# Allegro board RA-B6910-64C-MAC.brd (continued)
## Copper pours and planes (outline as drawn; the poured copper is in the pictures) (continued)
Net_297 on SIG8: 408.66,43.3 408.66,41.77 410.18,41.77 410.18,43.3
Net_298 on GND9: 408.66,43.3 408.66,41.77 410.18,41.77 410.18,43.3
Net_299 on SIG9: 408.66,43.3 408.66,41.77 410.18,41.77 410.18,43.3
Net_300 on GND10: 408.66,43.3 408.66,41.77 410.18,41.77 410.18,43.3
Net_301 on SIG10: 408.66,43.3 408.66,41.77 410.18,41.77 410.18,43.3
Net_302 on GND11: 408.66,43.3 408.66,41.77 410.18,41.77 410.18,43.3
Net_303 on POWER2: 408.66,43.3 408.66,41.77 410.18,41.77 410.18,43.3
Net_304 on GND12: 408.66,43.3 408.66,41.77 410.18,41.77 410.18,43.3
Net_305 on POWER1: 405.61,43.3 405.61,41.77 407.13,41.77 407.13,43.3
Net_306 on GND2: 405.61,43.3 405.61,41.77 407.13,41.77 407.13,43.3
Net_307 on SIG2: 405.61,43.3 405.61,41.77 407.13,41.77 407.13,43.3
Net_308 on GND3: 405.61,43.3 405.61,41.77 407.13,41.77 407.13,43.3
Net_309 on SIG9: 414.75,43.3 414.75,41.77 416.28,41.77 416.28,43.3
Net_310 on GND10: 414.75,43.3 414.75,41.77 416.28,41.77 416.28,43.3
Net_311 on SIG10: 414.75,43.3 414.75,41.77 416.28,41.77 416.28,43.3
Net_312 on GND11: 414.75,43.3 414.75,41.77 416.28,41.77 416.28,43.3
Net_313 on POWER2: 414.75,43.3 414.75,41.77 416.28,41.77 416.28,43.3
Net_314 on GND12: 414.75,43.3 414.75,41.77 416.28,41.77 416.28,43.3
Net_315 on POWER1: 414.75,40.25 414.75,38.72 416.28,38.72 416.28,40.25
Net_316 on GND2: 414.75,40.25 414.75,38.72 416.28,38.72 416.28,40.25
Net_317 on SIG2: 414.75,40.25 414.75,38.72 416.28,38.72 416.28,40.25
Net_318 on GND3: 414.75,40.25 414.75,38.72 416.28,38.72 416.28,40.25
Net_319 on SIG3: 414.75,40.25 414.75,38.72 416.28,38.72 416.28,40.25
Net_320 on GND4: 414.75,40.25 414.75,38.72 416.28,38.72 416.28,40.25
Net_321 on SIG4: 414.75,40.25 414.75,38.72 416.28,38.72 416.28,40.25
Net_322 on GND5: 414.75,40.25 414.75,38.72 416.28,38.72 416.28,40.25
Net_323 on SIG5: 414.75,40.25 414.75,38.72 416.28,38.72 416.28,40.25
Net_324 on GND6: 414.75,40.25 414.75,38.72 416.28,38.72 416.28,40.25
Net_325 on SIG6: 414.75,40.25 414.75,38.72 416.28,38.72 416.28,40.25
Net_326 on GND7: 414.75,40.25 414.75,38.72 416.28,38.72 416.28,40.25
Net_327 on SIG7: 414.75,40.25 414.75,38.72 416.28,38.72 416.28,40.25
Net_328 on GND8: 414.75,40.25 414.75,38.72 416.28,38.72 416.28,40.25
Net_329 on SIG8: 414.75,40.25 414.75,38.72 416.28,38.72 416.28,40.25
Net_330 on GND9: 414.75,40.25 414.75,38.72 416.28,38.72 416.28,40.25
Net_331 on GND5: 411.71,37.2 411.71,35.68 413.23,35.68 413.23,37.2
Net_332 on GND4: 411.71,37.2 411.71,35.68 413.23,35.68 413.23,37.2
Net_333 on GND3: 411.71,37.2 411.71,35.68 413.23,35.68 413.23,37.2
Net_334 on SIG2: 411.71,37.2 411.71,35.68 413.23,35.68 413.23,37.2
Net_335 on GND2: 411.71,37.2 411.71,35.68 413.23,35.68 413.23,37.2
Net_336 on GND5: 414.75,37.2 414.75,35.68 416.28,35.68 416.28,37.2
Net_337 on GND4: 414.75,37.2 414.75,35.68 416.28,35.68 416.28,37.2
Net_338 on GND3: 414.75,37.2 414.75,35.68 416.28,35.68 416.28,37.2
Net_339 on SIG2: 414.75,37.2 414.75,35.68 416.28,35.68 416.28,37.2
Net_340 on GND2: 414.75,37.2 414.75,35.68 416.28,35.68 416.28,37.2
Net_341 on POWER1: 414.75,37.2 414.75,35.68 416.28,35.68 416.28,37.2
Net_342 on POWER1: 411.71,37.2 411.71,35.68 413.23,35.68 413.23,37.2
Net_343 on SIG8: 414.75,46.34 414.75,44.82 416.28,44.82 416.28,46.34
Net_344 on GND8: 414.75,46.34 414.75,44.82 416.28,44.82 416.28,46.34
Net_345 on SIG7: 414.75,46.34 414.75,44.82 416.28,44.82 416.28,46.34
Net_346 on GND7: 414.75,46.34 414.75,44.82 416.28,44.82 416.28,46.34
Net_347 on SIG6: 414.75,46.34 414.75,44.82 416.28,44.82 416.28,46.34
Net_348 on GND6: 414.75,46.34 414.75,44.82 416.28,44.82 416.28,46.34
Net_349 on SIG5: 414.75,46.34 414.75,44.82 416.28,44.82 416.28,46.34
Net_350 on GND5: 414.75,46.34 414.75,44.82 416.28,44.82 416.28,46.34
Net_351 on SIG4: 414.75,46.34 414.75,44.82 416.28,44.82 416.28,46.34
Net_352 on GND4: 414.75,46.34 414.75,44.82 416.28,44.82 416.28,46.34
Net_353 on SIG3: 414.75,46.34 414.75,44.82 416.28,44.82 416.28,46.34
Net_354 on GND3: 414.75,46.34 414.75,44.82 416.28,44.82 416.28,46.34
Net_355 on SIG2: 414.75,46.34 414.75,44.82 416.28,44.82 416.28,46.34
Net_356 on GND2: 414.75,46.34 414.75,44.82 416.28,44.82 416.28,46.34
Net_357 on POWER1: 414.75,46.34 414.75,44.82 416.28,44.82 416.28,46.34
Net_358 on SIG1: 414.75,46.34 414.75,44.82 416.28,44.82 416.28,46.34
Net_359 on GND12: 411.71,46.34 411.71,44.82 413.23,44.82 413.23,46.34
Net_360 on POWER2: 411.71,46.34 411.71,44.82 413.23,44.82 413.23,46.34
Net_361 on GND11: 411.71,46.34 411.71,44.82 413.23,44.82 413.23,46.34
Net_362 on SIG10: 411.71,46.34 411.71,44.82 413.23,44.82 413.23,46.34
Net_363 on GND10: 411.71,46.34 411.71,44.82 413.23,44.82 413.23,46.34
Net_364 on SIG9: 411.71,46.34 411.71,44.82 413.23,44.82 413.23,46.34
Net_365 on GND9: 411.71,46.34 411.71,44.82 413.23,44.82 413.23,46.34
Net_366 on SIG8: 411.71,46.34 411.71,44.82 413.23,44.82 413.23,46.34
Net_367 on GND8: 411.71,46.34 411.71,44.82 413.23,44.82 413.23,46.34
Net_368 on SIG7: 411.71,46.34 411.71,44.82 413.23,44.82 413.23,46.34
Net_369 on GND7: 411.71,46.34 411.71,44.82 413.23,44.82 413.23,46.34
Net_370 on SIG6: 411.71,46.34 411.71,44.82 413.23,44.82 413.23,46.34
Net_371 on GND6: 411.71,46.34 411.71,44.82 413.23,44.82 413.23,46.34
Net_372 on SIG5: 411.71,46.34 411.71,44.82 413.23,44.82 413.23,46.34
Net_373 on SIG9: 414.75,40.25 414.75,38.72 416.28,38.72 416.28,40.25
Net_374 on GND10: 414.75,40.25 414.75,38.72 416.28,38.72 416.28,40.25
Net_375 on SIG10: 414.75,40.25 414.75,38.72 416.28,38.72 416.28,40.25
Net_376 on GND11: 414.75,40.25 414.75,38.72 416.28,38.72 416.28,40.25
Net_377 on POWER2: 414.75,40.25 414.75,38.72 416.28,38.72 416.28,40.25
Net_378 on GND12: 414.75,40.25 414.75,38.72 416.28,38.72 416.28,40.25
Net_379 on SIG1: 414.75,40.25 414.75,38.72 416.28,38.72 416.28,40.25
Net_380 on SIG1: 414.75,43.3 414.75,41.77 416.28,41.77 416.28,43.3
Net_381 on POWER1: 411.71,43.3 411.71,41.77 413.23,41.77 413.23,43.3
Net_382 on GND2: 411.71,43.3 411.71,41.77 413.23,41.77 413.23,43.3
Net_383 on SIG2: 411.71,43.3 411.71,41.77 413.23,41.77 413.23,43.3
Net_384 on GND3: 411.71,43.3 411.71,41.77 413.23,41.77 413.23,43.3
Net_385 on SIG3: 411.71,43.3 411.71,41.77 413.23,41.77 413.23,43.3
Net_386 on GND4: 411.71,43.3 411.71,41.77 413.23,41.77 413.23,43.3
Net_387 on SIG4: 411.71,43.3 411.71,41.77 413.23,41.77 413.23,43.3
Net_388 on GND5: 411.71,43.3 411.71,41.77 413.23,41.77 413.23,43.3
Net_389 on SIG5: 411.71,43.3 411.71,41.77 413.23,41.77 413.23,43.3
Net_390 on GND6: 411.71,43.3 411.71,41.77 413.23,41.77 413.23,43.3
Net_391 on SIG6: 411.71,43.3 411.71,41.77 413.23,41.77 413.23,43.3
Net_392 on GND7: 411.71,43.3 411.71,41.77 413.23,41.77 413.23,43.3
Net_393 on SIG7: 411.71,43.3 411.71,41.77 413.23,41.77 413.23,43.3
Net_394 on GND8: 411.71,43.3 411.71,41.77 413.23,41.77 413.23,43.3
Net_395 on SIG8: 411.71,43.3 411.71,41.77 413.23,41.77 413.23,43.3
Net_396 on GND9: 411.71,43.3 411.71,41.77 413.23,41.77 413.23,43.3
Net_397 on SIG9: 411.71,43.3 411.71,41.77 413.23,41.77 413.23,43.3
Net_398 on GND10: 411.71,43.3 411.71,41.77 413.23,41.77 413.23,43.3
Net_399 on SIG10: 411.71,43.3 411.71,41.77 413.23,41.77 413.23,43.3
Net_400 on GND11: 411.71,43.3 411.71,41.77 413.23,41.77 413.23,43.3
Net_401 on POWER2: 411.71,43.3 411.71,41.77 413.23,41.77 413.23,43.3
Net_402 on GND12: 411.71,43.3 411.71,41.77 413.23,41.77 413.23,43.3
Net_403 on POWER1: 411.71,40.25 411.71,38.72 413.23,38.72 413.23,40.25
Net_404 on GND2: 411.71,40.25 411.71,38.72 413.23,38.72 413.23,40.25
Net_405 on SIG2: 411.71,40.25 411.71,38.72 413.23,38.72 413.23,40.25
Net_406 on GND3: 411.71,40.25 411.71,38.72 413.23,38.72 413.23,40.25
Net_407 on SIG3: 411.71,40.25 411.71,38.72 413.23,38.72 413.23,40.25
Net_408 on GND4: 411.71,40.25 411.71,38.72 413.23,38.72 413.23,40.25
Net_409 on SIG4: 411.71,40.25 411.71,38.72 413.23,38.72 413.23,40.25
Net_410 on GND5: 411.71,40.25 411.71,38.72 413.23,38.72 413.23,40.25
Net_411 on SIG5: 411.71,40.25 411.71,38.72 413.23,38.72 413.23,40.25
Net_412 on GND6: 411.71,40.25 411.71,38.72 413.23,38.72 413.23,40.25
Net_413 on SIG6: 411.71,40.25 411.71,38.72 413.23,38.72 413.23,40.25
Net_414 on GND7: 411.71,40.25 411.71,38.72 413.23,38.72 413.23,40.25
Net_415 on SIG7: 411.71,40.25 411.71,38.72 413.23,38.72 413.23,40.25
Net_416 on GND8: 411.71,40.25 411.71,38.72 413.23,38.72 413.23,40.25
Net_417 on SIG8: 411.71,40.25 411.71,38.72 413.23,38.72 413.23,40.25
Net_418 on GND9: 411.71,40.25 411.71,38.72 413.23,38.72 413.23,40.25
Net_419 on SIG9: 411.71,40.25 411.71,38.72 413.23,38.72 413.23,40.25
Net_420 on GND10: 411.71,40.25 411.71,38.72 413.23,38.72 413.23,40.25
Net_421 on SIG10: 411.71,40.25 411.71,38.72 413.23,38.72 413.23,40.25
Net_422 on GND11: 411.71,40.25 411.71,38.72 413.23,38.72 413.23,40.25
Net_423 on POWER2: 411.71,40.25 411.71,38.72 413.23,38.72 413.23,40.25
Net_424 on GND12: 411.71,40.25 411.71,38.72 413.23,38.72 413.23,40.25
Net_425 on SIG1: 411.71,40.25 411.71,38.72 413.23,38.72 413.23,40.25
Net_426 on SIG1: 411.71,43.3 411.71,41.77 413.23,41.77 413.23,43.3
Net_427 on POWER1: 414.75,43.3 414.75,41.77 416.28,41.77 416.28,43.3
Net_428 on GND2: 414.75,43.3 414.75,41.77 416.28,41.77 416.28,43.3
Net_429 on SIG2: 414.75,43.3 414.75,41.77 416.28,41.77 416.28,43.3
Net_430 on GND3: 414.75,43.3 414.75,41.77 416.28,41.77 416.28,43.3
Net_431 on SIG3: 414.75,43.3 414.75,41.77 416.28,41.77 416.28,43.3
Net_432 on GND4: 414.75,43.3 414.75,41.77 416.28,41.77 416.28,43.3
Net_433 on SIG4: 414.75,43.3 414.75,41.77 416.28,41.77 416.28,43.3
Net_434 on GND5: 414.75,43.3 414.75,41.77 416.28,41.77 416.28,43.3
Net_435 on SIG5: 414.75,43.3 414.75,41.77 416.28,41.77 416.28,43.3
Net_436 on GND6: 414.75,43.3 414.75,41.77 416.28,41.77 416.28,43.3
Net_437 on SIG6: 414.75,43.3 414.75,41.77 416.28,41.77 416.28,43.3
Net_438 on GND7: 414.75,43.3 414.75,41.77 416.28,41.77 416.28,43.3
Net_439 on SIG7: 414.75,43.3 414.75,41.77 416.28,41.77 416.28,43.3
Net_440 on GND8: 414.75,43.3 414.75,41.77 416.28,41.77 416.28,43.3
Net_441 on SIG8: 414.75,43.3 414.75,41.77 416.28,41.77 416.28,43.3
Net_442 on GND9: 414.75,43.3 414.75,41.77 416.28,41.77 416.28,43.3
Net_443 on GND5: 411.71,46.34 411.71,44.82 413.23,44.82 413.23,46.34
Net_444 on SIG4: 411.71,46.34 411.71,44.82 413.23,44.82 413.23,46.34
Net_445 on GND4: 411.71,46.34 411.71,44.82 413.23,44.82 413.23,46.34
Net_446 on SIG3: 411.71,46.34 411.71,44.82 413.23,44.82 413.23,46.34
Net_447 on GND3: 411.71,46.34 411.71,44.82 413.23,44.82 413.23,46.34
Net_448 on SIG2: 411.71,46.34 411.71,44.82 413.23,44.82 413.23,46.34
Net_449 on GND2: 411.71,46.34 411.71,44.82 413.23,44.82 413.23,46.34
Net_450 on POWER1: 411.71,46.34 411.71,44.82 413.23,44.82 413.23,46.34
Net_451 on SIG1: 411.71,46.34 411.71,44.82 413.23,44.82 413.23,46.34
Net_452 on GND12: 414.75,46.34 414.75,44.82 416.28,44.82 416.28,46.34
Net_453 on POWER2: 414.75,46.34 414.75,44.82 416.28,44.82 416.28,46.34
Net_454 on GND11: 414.75,46.34 414.75,44.82 416.28,44.82 416.28,46.34
Net_455 on SIG10: 414.75,46.34 414.75,44.82 416.28,44.82 416.28,46.34
Net_456 on GND10: 414.75,46.34 414.75,44.82 416.28,44.82 416.28,46.34
Net_457 on SIG9: 414.75,46.34 414.75,44.82 416.28,44.82 416.28,46.34
Net_458 on GND9: 414.75,46.34 414.75,44.82 416.28,44.82 416.28,46.34
Net_459 on TOP (solid shape): outline of 184 points within 387.8,37.08 391.35,40.64
Net_460 on BOTTOM (solid shape): outline of 184 points within 387.8,37.08 391.35,40.64
Net_461 on BOTTOM (solid shape): outline of 184 points within 411.95,212.07 415.51,215.62
Net_462 on TOP (solid shape): outline of 184 points within 411.95,212.07 415.51,215.62
PCIE_PVDD0P8 on TOP: 165.93,184.78 165.93,183.13 165.54,182.75 161.35,182.75 161.23,182.88 161.23,184.78 161.35,184.91 165.8,184.91
PCIE_PVDD0P8 on SIG3: 185.36,181.99 189.67,177.67 189.67,168.27 188.91,167.51 188.91,157.22 189.42,156.72 193.74,156.72 194.12,157.1 194.12,157.86 193.23,158.75 193.23,167.13 192.21,168.15 192.21,178.18 185.48,184.91 164.66,184.91 164.65,184.91 161.92,184.91 161.64,184.63 161.64,182.71 162.36,181.99
PCIE_TRVDD0P8 on TOP: 209.99,192.78 211.66,192.78 211.66,194.07 211.9,194.31 211.9,196.34 211.77,196.47 209.99,196.47 209.87,196.34 209.87,192.91
PCIE_TRVDD0P8 on SIG8: 200.09,164.72 202.76,164.72 203.14,165.1 203.14,179.58 212.41,188.85 212.41,194.05 212.03,194.43 208.6,194.43 208.22,194.05 208.22,190.75 199.96,182.5 199.96,164.84
PH1 on TOP (solid shape): 79.27,135.09 84.68,135.09 85.03,134.74 85.03,131.44 84.75,131.16 73.04,131.16 72.78,131.42 72.78,134.97 72.91,135.1 79.26,135.1
PH2 on TOP (solid shape): 79.27,145.25 84.68,145.25 85.03,144.9 85.03,141.73 84.62,141.32 73.04,141.32 72.78,141.58 72.78,145.13 72.91,145.26 79.26,145.26
PH3 on TOP (solid shape): 84.83,155.03 84.83,151.94 84.38,151.48 73.04,151.48 72.78,151.74 72.78,155.29 72.91,155.42 84.44,155.42
PH4 on TOP (solid shape): 84.83,165.18 84.83,162.28 84.2,161.64 73.04,161.64 72.78,161.9 72.78,165.45 72.91,165.58 84.43,165.58
PH5 on TOP (solid shape): 84.88,175.41 84.88,172.2 84.49,171.8 73.04,171.8 72.78,172.06 72.78,175.61 72.91,175.74 84.55,175.74
PH6 on TOP (solid shape): 84.85,185.67 84.85,182.39 84.42,181.96 73.04,181.96 72.78,182.22 72.78,185.77 72.91,185.9 84.62,185.9
PH7 on TOP (solid shape): 343.31,144.57 343.31,141.02 343.18,140.89 331.15,140.89 330.9,141.14 330.9,144.7 331.03,144.83 343.06,144.83
PH8 on TOP (solid shape): 343.31,134.41 343.31,130.86 343.18,130.73 331.1,130.73 330.9,130.93 330.9,134.41 331.15,134.67 343.06,134.67
PH9 on TOP (solid shape): 343.31,164.89 343.31,161.34 343.18,161.21 331.1,161.21 330.9,161.41 330.9,165.02 331.03,165.15 343.06,165.15
PH10 on TOP (solid shape): 343.31,154.73 343.31,151.18 343.18,151.05 331.15,151.05 330.9,151.3 330.9,154.86 331.03,154.99 343.06,154.99
PH11 on TOP: 331.03,185.67 343.09,185.67 343.34,185.42 343.34,181.61 343.09,181.35 331.03,181.35 330.77,181.61 330.77,185.42
PH12 on TOP (solid shape): 343.31,175.05 343.31,171.5 343.18,171.37 331.1,171.37 330.9,171.57 330.9,175.05 331.15,175.31 343.06,175.31
PVTMON_AVDD1P8 on TOP: 186.37,178.69 187.52,177.54 187.52,175.53 186.61,174.62 186.4,174.62 185.32,175.7 183.89,175.7 182.18,177.42 182.18,178.43 182.44,178.69
PVTMON_AVDD1P8 on SIG8: 216.47,153.92 216.85,153.54 216.85,125.98 216.47,125.6 193.01,125.6 192.16,126.45 184.54,126.45 183.7,125.6 178.75,125.6 178.24,126.11 178.24,138.38 179.77,139.9 179.77,149.98 177.74,152.02 177.74,153.79 177.99,154.05 179.26,154.05 183.83,158.62 183.83,175.26 184.47,175.89 185.99,175.89 186.75,175.13 186.75,173.48 186.25,172.97 186.25,160.27 186.5,160.02 187.9,160.02 189.17,158.75 189.17,156.97 189.18,156.96 189.18,155.51 190.76,153.92
RESCAL_AVDD0P8 on TOP: 180.53,178.69 180.66,178.56 180.66,177.24 181.01,177.24 182.86,175.38 185.31,175.38 186.31,174.38 186.68,174.38 187.86,175.57 193.12,175.57 193.39,175.3 193.39,173.96 193.19,173.76 188.46,173.76 187.88,173.17 186.19,173.17 185.65,173.72 179.15,173.72 176.09,176.78 176.09,178.56 176.21,178.69
RESCAL_AVDD0P8 on SIG10: 177.99,154.94 179.9,154.94 180.78,154.05 191.45,154.05 191.83,154.43 191.83,173.14 190.72,174.25 190.72,175.1 191.24,175.63 195.53,175.63 197.29,173.86 197.29,152.4 198.44,151.25 214.44,151.25 215.84,152.65 215.84,154.94 215.96,155.06 217.67,155.06 217.92,154.82 217.92,148.89 215.2,146.17 215.2,133.09 217.23,131.06 217.23,126.87 217.11,126.74 178.5,126.74 177.86,127.38 177.86,154.81
TS_PLL_AVDD1P8 on TOP: 223.33,192.78 225.11,192.78 225.23,192.91 225.23,194.69 225.11,194.82 223.33,194.82 223.2,194.69 223.2,192.91
TS_PLL_AVDD1P8 on SIG8: 196.91,154.05 200.6,154.05 200.85,154.3 200.85,162.3 199.58,163.57 199.58,182.75 207.58,190.75 207.58,194.43 208.09,194.94 220.66,194.94 222.95,192.66 224.73,192.66 224.85,192.78 224.85,197.48 223.84,198.5 204.79,198.5 201.49,195.2 201.49,189.74 196.66,184.91 196.66,154.3
USB5V on TOP: 391.86,214.17 391.86,216.07 391.73,216.2 388.81,216.2 388.68,216.33 388.68,223.56 388.3,223.95 386.52,223.95 386.14,223.56 386.14,216.58 385.61,216.05 385.61,215.54 385.89,215.26 386.68,215.26 387.92,214.02 391.71,214.02
USB5V on TOP: 394.91,26.79 396.68,26.79 396.81,26.92 396.81,29.84 396.68,29.97 394.91,29.97 394.78,29.84 394.78,26.92
USB5V on BOTTOM: 383.48,212.72 391.48,212.72 391.86,213.1 391.86,221.87 390.59,223.14 386.27,223.14 385.51,222.37 385.51,219.96 383.22,217.68 383.22,212.98
USB5V on SIG2: 394.85,27.56 396.47,27.56 396.91,27.99 396.91,48.17 397.61,48.87 398.56,48.87 411.67,61.97 411.67,214.25 408.62,217.29 399.48,217.29 393.76,223.01 385.64,223.01 384.62,221.99 384.62,217.55 385.38,216.79 385.38,204.21 393.38,196.21 393.38,67.05 388.68,62.35 388.68,33.72
VMON_PWM_OUT on SIG4: 27.24,173.1 28.89,171.45 28.89,167.76 31.05,165.61 31.05,157.1 30.42,156.46 26.61,156.46 25.59,157.48 25.59,165.99 21.15,170.43 14.67,170.43 14.29,170.81 14.29,172.84 14.54,173.1
ZQSFP+1_3.3V on TOP (solid shape): 20.97,110.11 21,110.09 21.02,110.06 21.02,109.42 21.88,109.42 21.88,110.06 21.9,110.09 21.93,110.11 22.21,110.11 22.25,110.09 22.26,110.06 22.26,109.42 23.13,109.42 23.13,110.06 23.14,110.09 23.18,110.11 23.33,110.11 23.37,110.09 23.38,110.06 23.38,109.42 24.25,109.42 24.25,110.06 24.26,110.09 24.3,110.11 24.83,110.11 25.34,109.6 29.02,109.6 29.27,109.34 29.27,105.53 28.33,104.59 28.22,104.57 28.16,104.65 27.51,104.89 27.74,104.24 27.83,104.17 27.81,104.07 27.62,103.88 27.11,103.88 26.73,103.5 26.73,102.49 26.23,101.98 25.87,101.98 25.85,102 25.84,102.02 25.46,102.36 25.08,102.02 25.07,101.99 25.03,101.98 7.81,101.98 7.3,102.49 7.3,109.47 7.94,110.11
ZQSFP+1_3.3V on BOTTOM (solid shape): 26.73,109.85 26.73,106.04 26.23,105.53 23.43,105.53 23.18,105.28 23.18,102.23 22.92,101.98 7.81,101.98 7.3,102.49 7.3,103.38 7.05,103.63 4.89,103.63 4.64,103.88 4.64,105.79 4.89,106.04 6.92,106.04 7.3,106.42 7.3,109.47 7.94,110.11 26.48,110.11
ZQSFP+1_3.3V on TOP: 49.21,90.8 49.59,90.42 49.59,85.98 49.47,85.85 48.32,85.85 48.13,86.04 48.13,86.93 47.56,87.5 46.8,87.5 46.55,87.75 46.55,90.55 46.8,90.8
ZQSFP+1_3.3V on TOP: 13.14,83.56 9.46,83.56 9.33,83.69 9.33,87.9 9.44,88.01 13.16,88.01 13.27,87.9 13.27,87.37 13.27,87.37 13.27,83.69
ZQSFP+1_3.3V on TOP: 13.02,77.47 9.33,77.47 9.21,77.59 9.21,79.25 9.59,79.63 12.76,79.63 13.14,79.25 13.14,77.59
ZQSFP+1_3.3V on TOP: 28.87,93.41 28.45,93.41 28.32,93.53 28.32,95.18 28.7,95.56 31.88,95.56 32.26,95.18 32.26,93.53 31.83,93.1 29.18,93.1
ZQSFP+1_3.3V on TOP: 32.26,99.57 28.58,99.57 28.45,99.69 28.45,103.38 29.72,104.65 31.81,104.65 32.39,104.07 32.39,99.69
ZQSFP+1_3.3V on TOP: 67.25,86.87 63.56,86.87 63.44,86.99 63.44,90.68 63.69,90.93 67.12,90.93 67.37,90.68 67.37,86.99
ZQSFP+1_3.3V on TOP: 89.85,87.12 89.85,90.68 90.11,90.93 93.54,90.93 93.79,90.68 93.79,87.12 93.66,86.99 89.98,86.99
ZQSFP+1_3.3V on TOP: 49.47,81.02 45.78,81.02 45.66,81.15 45.66,82.42 45.78,82.55 46.55,82.55 47.18,83.18 49.21,83.18 49.59,82.8 49.59,81.15
ZQSFP+1_3.3V on TOP, BOTTOM: 67.25,81.02 63.56,81.02 63.44,81.15 63.44,82.8 63.82,83.18 66.99,83.18 67.37,82.8 67.37,81.15
ZQSFP+1_3.3V on TOP, BOTTOM: 89.85,81.4 89.85,82.8 90.23,83.18 90.74,83.18 91.25,83.69 92.39,83.69 92.9,83.18 93.41,83.18 93.79,82.8 93.79,81.4 93.66,81.28 89.98,81.28
ZQSFP+1_3.3V on TOP, BOTTOM: 80.45,86.87 76.77,86.87 76.64,86.99 76.64,90.68 76.9,90.93 80.33,90.93 80.58,90.68 80.58,86.99
ZQSFP+1_3.3V on TOP, BOTTOM: 80.45,81.02 76.77,81.02 76.64,81.15 76.64,82.8 77.03,83.18 80.2,83.18 80.58,82.8 80.58,81.15
ZQSFP+1_3.3V on BOTTOM: 89.85,87.12 89.85,92.71 90.23,93.09 100.52,93.09 100.9,92.71 100.9,87.25 100.65,86.99 99.12,86.99 99,87.12 99,90.68 98.23,91.44 93.92,91.44 93.79,91.31 93.79,87.12 93.66,86.99 89.98,86.99
ZQSFP+1_3.3V on BOTTOM: 13.08,77.66 9.4,77.66 9.27,77.78 9.27,79.44 9.65,79.82 12.83,79.82 13.21,79.44 13.21,77.78
ZQSFP+1_3.3V on BOTTOM: 30.61,93.09 30.29,93.41 28.45,93.41 28.32,93.53 28.32,95.18 28.7,95.56 30.73,95.56 31.26,96.09 33.27,96.09 33.46,95.9 33.46,95.67 33.06,95.28 32.83,95.28 32.58,95.03 32.58,93.34 32.32,93.09
ZQSFP+1_3.3V on BOTTOM: 13.08,83.69 9.4,83.69 9.27,83.82 9.27,87.37 9.53,87.63 13.08,87.63 13.21,87.5 13.21,83.82
ZQSFP+1_3.3V on BOTTOM: 49.47,81.02 45.78,81.02 45.66,81.15 45.66,82.8 46.04,83.18 49.21,83.18 49.59,82.8 49.59,81.15
ZQSFP+1_3.3V on BOTTOM: 67.25,86.87 63.56,86.87 63.44,86.99 63.44,93.47 63.69,93.72 66.99,93.72 67.37,93.34 67.37,86.99
ZQSFP+1_3.3V on BOTTOM: 32.26,99.57 28.58,99.57 28.45,99.69 28.45,104.14 28.96,104.65 31.88,104.65 32.39,104.14 32.39,99.69
ZQSFP+1_3.3V on BOTTOM: 49.53,87.12 45.85,87.12 45.72,87.25 45.72,92.58 45.97,92.83 49.28,92.83 49.66,92.45 49.66,87.25
ZQSFP+1_3.3V on BOTTOM: 40.96,98.42 40.96,93.85 40.58,93.47 38.54,93.47 38.29,93.72 38.29,95.12 37.66,95.76 37.66,98.42 37.91,98.68 40.7,98.68
ZQSFP+1_3.3V on POWER1: 1.02,112.25 1.93,113.15 41.08,113.15 41.08,106 37.53,102.44 37.53,99.36 39.31,97.58 39.31,94.91 42.78,91.44 51.03,91.44 52.69,89.79 63.14,89.79 64.54,91.18 74.28,91.18 74.91,90.55 78.25,90.55 78.63,90.93 81.39,90.93 83.93,88.39 87.27,88.39 90.06,91.18 91.8,91.18 92.27,90.72 92.27,69.39 92.24,69.36 92.24,52.42 91.76,51.94 15.56,51.94 12.64,54.86 2.35,54.86 1.02,56.2
ZQSFP+2_3.3V on TOP (solid shape): 48.65,117.09 48.69,117.08 48.7,117.04 48.7,116.41 49.57,116.41 49.57,117.04 49.58,117.08 49.62,117.09 49.9,117.09 49.93,117.08 49.95,117.04 49.95,116.41 50.81,116.41 50.81,117.04 50.83,117.08 50.86,117.09 51.02,117.09 51.05,117.08 51.07,117.04 51.07,116.41 51.93,116.41 51.93,117.04 51.95,117.08 51.98,117.09 54.17,117.09 54.42,116.84 54.42,109.34 53.91,108.84 35.5,108.84 34.99,109.34 34.99,116.46 35.62,117.09
ZQSFP+2_3.3V on BOTTOM (solid shape): 54.42,116.84 54.42,110.87 52.64,109.09 36.26,109.09 34.73,110.61 32.58,110.61 32.32,110.87 32.32,112.77 32.58,113.03 34.61,113.03 34.99,113.41 34.99,116.46 35.62,117.09 54.17,117.09
ZQSFP+2_3.3V on TOP: 170.62,90.68 171.01,91.06 174.18,91.06 174.56,90.68 174.56,86.48 174.43,86.36 170.75,86.36 170.62,86.48
ZQSFP+2_3.3V on TOP: 130.24,86.87 126.56,86.87 126.43,86.99 126.43,90.68 126.68,90.93 130.11,90.93 130.37,90.68 130.37,86.99
ZQSFP+2_3.3V on TOP: 130.24,81.02 126.56,81.02 126.43,81.15 126.43,82.42 127.19,83.18 129.98,83.18 130.37,82.8 130.37,81.15
ZQSFP+2_3.3V on TOP: 187.64,81.02 183.96,81.02 183.83,81.15 183.83,82.8 184.21,83.18 187.39,83.18 187.77,82.8 187.77,81.15
ZQSFP+2_3.3V on TOP: 187.64,86.87 183.96,86.87 183.83,86.99 183.83,90.68 184.21,91.06 187.39,91.06 187.77,90.68 187.77,86.99
ZQSFP+2_3.3V on TOP: 174.43,81.02 170.75,81.02 170.62,81.15 170.62,82.8 170.92,83.1 174.27,83.1 174.56,82.8 174.56,81.15
ZQSFP+2_3.3V on TOP: 143.45,86.87 139.76,86.87 139.64,86.99 139.64,90.93 139.76,91.06 143.32,91.06 143.57,90.8 143.57,86.99
ZQSFP+2_3.3V on TOP: 161.23,86.87 157.67,86.87 157.54,86.99 157.54,88.77 157.16,89.15 157.16,91.18 157.54,91.56 157.54,97.53 157.8,97.79 161.23,97.79 161.35,97.66 161.35,86.99
ZQSFP+2_3.3V on TOP: 113.22,90.68 113.6,91.06 116.78,91.06 117.16,90.68 117.16,86.74 116.9,86.48 113.35,86.48 113.22,86.61
ZQSFP+2_3.3V on TOP, BOTTOM: 161.23,81.02 157.54,81.02 157.42,81.15 157.42,82.8 157.8,83.18 160.97,83.18 161.35,82.8 161.35,81.15
ZQSFP+2_3.3V on TOP, BOTTOM: 113.22,81.28 113.22,82.8 113.6,83.18 116.78,83.18 117.16,82.8 117.16,81.28 117.03,81.15 116.14,81.15 115.38,80.39 114.74,80.39 113.98,81.15 113.35,81.15
ZQSFP+2_3.3V on TOP, BOTTOM: 143.45,81.02 139.76,81.02 139.64,81.15 139.64,82.8 140.02,83.18 143.19,83.18 143.57,82.8 143.57,81.15
ZQSFP+2_3.3V on BOTTOM: 126.56,86.87 126.43,86.99 126.43,96.01 130.87,100.45 137.6,100.45 137.73,100.33 137.73,98.68 137.6,98.55 135.95,98.55 135.45,98.04 133.03,98.04 130.37,95.37 130.37,86.99 130.24,86.87
ZQSFP+2_3.3V on BOTTOM: 170.62,90.68 170.88,90.93 174.31,90.93 174.56,90.68 174.56,86.48 174.43,86.36 170.75,86.36 170.62,86.48
ZQSFP+2_3.3V on BOTTOM: 137.35,93.85 135.95,93.85 135.45,93.34 133.29,93.34 133.16,93.47 133.16,95.25 133.29,95.37 137.35,95.37 137.48,95.25 137.48,93.98
ZQSFP+2_3.3V on BOTTOM: 141.8,86.87 139.76,86.87 139.64,86.99 139.64,90.93 139.76,91.06 141.92,91.06 142.18,90.8 142.18,87.25
ZQSFP+2_3.3V on BOTTOM: 187.64,86.87 183.96,86.87 183.83,86.99 183.83,90.68 184.09,90.93 187.52,90.93 187.77,90.68 187.77,86.99
ZQSFP+2_3.3V on BOTTOM: 194.25,89.91 192.92,89.91 192.72,89.71 192.72,88.77 192.98,88.52 192.98,87.12 193.1,86.99 194.25,86.99 194.37,87.12 194.37,89.79
ZQSFP+2_3.3V on BOTTOM: 130.24,81.02 126.56,81.02 126.43,81.15 126.43,82.8 126.81,83.18 129.98,83.18 130.37,82.8 130.37,81.15
ZQSFP+2_3.3V on BOTTOM: 183.83,82.8 184.21,83.18 186.12,83.18 186.25,83.06 186.25,81.02 186.12,80.9 183.96,80.9 183.83,81.02
ZQSFP+2_3.3V on BOTTOM: 174.43,81.02 170.75,81.02 170.62,81.15 170.62,82.8 171.01,83.18 174.18,83.18 174.56,82.8 174.56,81.15
ZQSFP+2_3.3V on BOTTOM: 113.22,91.18 113.09,91.31 108.65,91.31 108.27,90.93 108.27,87.12 108.14,86.99 106.62,86.99 106.36,87.25 106.36,92.83 106.62,93.09 116.65,93.09 117.16,92.58 117.16,86.74 116.9,86.48 113.35,86.48 113.22,86.61
ZQSFP+2_3.3V on POWER1: 48.01,116.71 63.99,116.71 71.48,109.22 98.28,109.22 106.53,100.96 127.11,100.96 130.16,97.91 153.4,97.91 158.6,92.71 194.97,92.71 195.14,92.88 195.14,55.75 191.07,51.69 190.06,51.69 188.91,52.83 188.02,52.83 186.88,51.69 180.78,51.69 179.51,52.96 178.37,52.96 177.1,51.69 162.24,51.69 160.97,52.96 159.19,52.96 157.92,51.69 143.07,51.69 141.8,52.96 141.03,52.96 139.76,51.69 133.79,51.69 132.27,53.21 131.64,53.21 130.11,51.69 114.49,51.69 113.35,52.83 112.59,52.83 111.44,51.69 94.81,51.69 93.28,53.21 93.28,91.14 92.22,92.2 89.64,92.2 86.85,89.41 84.35,89.41 81.81,91.95 78.21,91.95 77.83,91.56 75.33,91.56 74.7,92.2 64.12,92.2 62.72,90.8 53.11,90.8 51.46,92.45 43.2,92.45 40.32,95.33 40.32,98 38.54,99.78 38.54,102.02 42.1,105.58 42.1,115.66 43.5,117.07 47.65,117.07
ZQSFP+3_3.3V on TOP (solid shape): 407.48,155.32 407.48,137.03 406.97,136.52 397.45,136.52 396.94,137.03 396.94,147.01 396.95,147.05 396.99,147.06 397.63,147.06 397.63,147.93 396.99,147.93 396.95,147.94 396.94,147.98 396.94,148.26 396.95,148.29 396.99,148.31 397.63,148.31 397.63,149.17 396.99,149.17 396.95,149.19 396.94,149.22 396.94,149.37 396.95,149.41 396.99,149.43 397.63,149.43 397.63,150.29 396.99,150.29 396.95,150.3 396.94,150.34 396.94,150.62 397.57,151.25 397.57,155.57 397.83,155.83 406.97,155.83
ZQSFP+3_3.3V on TOP: 255.21,80.9 251.52,80.9 251.4,81.02 251.4,82.67 251.78,83.06 254.95,83.06 255.33,82.67 255.33,81.02
ZQSFP+3_3.3V on TOP: 281.62,86.87 277.94,86.87 277.81,86.99 277.81,91.06 278.07,91.31 281.5,91.31 281.75,91.06 281.75,86.99
ZQSFP+3_3.3V on TOP: 237.43,86.87 233.74,86.87 233.62,86.99 233.62,92.45 234.51,93.34 235.27,93.34 235.52,93.09 235.52,91.31 237.55,89.28 237.55,86.99
ZQSFP+3_3.3V on TOP: 233.62,82.8 234,83.18 237.17,83.18 237.55,82.8 237.55,81.02 237.43,80.9 233.74,80.9 233.62,81.02
ZQSFP+3_3.3V on TOP: 211.01,86.87 207.33,86.87 207.2,86.99 207.2,90.8 207.58,91.18 210.88,91.18 211.14,90.93 211.14,86.99
ZQSFP+3_3.3V on TOP: 255.21,86.87 251.52,86.87 251.4,86.99 251.4,90.68 251.78,91.06 253.56,91.06 253.94,91.44 253.94,93.34 253.56,93.72 251.78,93.72 251.52,93.98 251.52,95.76 251.65,95.88 255.21,95.88 255.33,95.76 255.33,86.99
ZQSFP+3_3.3V on TOP: 211.01,81.02 207.33,81.02 207.2,81.15 207.2,82.8 207.58,83.18 210.76,83.18 211.14,82.8 211.14,81.15
ZQSFP+3_3.3V on TOP: 268.41,86.87 264.73,86.87 264.6,86.99 264.6,90.68 264.86,90.93 268.29,90.93 268.54,90.68 268.54,86.99
ZQSFP+3_3.3V on TOP: 224.22,86.87 220.54,86.87 220.41,86.99 220.41,92.07 220.54,92.2 224.22,92.2 224.35,92.07 224.35,86.99
ZQSFP+3_3.3V on TOP, BOTTOM: 268.41,81.02 264.73,81.02 264.6,81.15 264.6,82.8 264.99,83.18 268.16,83.18 268.54,82.8 268.54,81.15
ZQSFP+3_3.3V on TOP, BOTTOM: 281.62,81.02 277.94,81.02 277.81,81.15 277.81,82.8 278.19,83.18 281.37,83.18 281.75,82.8 281.75,81.15
ZQSFP+3_3.3V on TOP, BOTTOM: 224.22,81.02 220.54,81.02 220.41,81.15 220.41,82.8 220.79,83.18 223.96,83.18 224.35,82.8 224.35,81.15
ZQSFP+3_3.3V on BOTTOM: 286.83,86.99 288.73,86.99 288.86,87.12 288.86,88.64 288.73,88.77 286.83,88.77 286.7,88.64 286.7,87.12
ZQSFP+3_3.3V on BOTTOM: 257.49,92.96 253.81,92.96 253.56,93.22 253.05,93.22 252.79,92.96 252.79,91.69 253.68,90.8 253.68,88.52 253.43,88.26 250.76,88.26 250.63,88.39 250.63,95.5 250.89,95.76 257.49,95.76 257.62,95.63 257.62,93.09
ZQSFP+3_3.3V on BOTTOM: 224.22,86.87 220.54,86.87 220.41,86.99 220.41,92.83 220.66,93.09 224.09,93.09 224.35,92.83 224.35,86.99
ZQSFP+3_3.3V on BOTTOM: 397.57,143.89 397.57,152.65 397.64,152.71 397.64,155.51 397.83,155.7 404.81,155.7 405.32,155.19 405.32,143.89 404.94,143.51 397.95,143.51
ZQSFP+3_3.3V on BOTTOM: 255.21,81.02 251.52,81.02 251.4,81.15 251.4,82.8 251.78,83.18 254.95,83.18 255.33,82.8 255.33,81.15
ZQSFP+3_3.3V on BOTTOM: 268.41,86.87 264.73,86.87 264.6,86.99 264.6,90.68 264.99,91.06 268.16,91.06 268.54,90.68 268.54,86.99
ZQSFP+3_3.3V on BOTTOM: 208.47,82.93 208.72,83.18 210.76,83.18 211.14,82.8 211.14,81.02 211.01,80.9 208.6,80.9 208.47,81.02
ZQSFP+3_3.3V on BOTTOM: 281.62,86.87 277.94,86.87 277.81,86.99 277.81,90.68 278.07,90.93 281.5,90.93 281.75,90.68 281.75,86.99
ZQSFP+3_3.3V on BOTTOM: 237.43,81.02 233.74,81.02 233.62,81.15 233.62,82.8 234,83.18 237.17,83.18 237.55,82.8 237.55,81.15
ZQSFP+3_3.3V on BOTTOM: 211.01,86.87 207.33,86.87 207.2,86.99 207.2,88.39 206.57,89.02 205.3,89.02 204.91,88.64 204.91,87.88 204.03,86.99 202.12,86.99 201.99,87.12 201.99,91.56 202.25,91.82 211.01,91.82 211.14,91.69 211.14,86.99
ZQSFP+3_3.3V on POWER1: 196.15,68.28 196.15,93.89 197.63,95.37 238.15,95.37 239.92,97.15 252.62,97.15 265.2,109.73 345.46,109.73 390.04,154.3 428.98,154.3 428.98,145.58 428.82,144.97 428.82,143.25 428.78,143.17 428.82,143.04 428.82,142.92 428.88,142.85 428.91,142.77 428.98,142.73 428.98,116.58 428.73,116.58 427.72,115.57 410.48,115.57 409.89,116.16 409.89,126.06 408.96,127 398.63,127 377,105.36 377,93.3 374,90.29 365.53,90.29 363.24,92.58 292.72,92.58 288.99,88.85 288.99,87.46 284.67,83.14 284.67,72.81 284.65,72.79 284.65,69.34 282.64,67.32 197.11,67.32
ZQSFP+4_3.3V on TOP (solid shape): 402.65,128.39 402.65,126.24 403.03,125.85 405.96,125.85 406.46,125.35 406.46,112.9 406.21,112.65 397.45,112.65 396.68,113.41 396.68,123.01 396.7,123.05 396.74,123.06 397.37,123.06 397.37,123.92 396.74,123.92 396.7,123.94 396.68,123.98 396.68,124.25 396.7,124.29 396.74,124.3 397.37,124.3 397.37,125.17 396.74,125.17 396.7,125.18 396.68,125.22 396.68,125.37 396.7,125.41 396.74,125.42 397.37,125.42 397.37,126.29 396.74,126.29 396.7,126.3 396.68,126.34 396.68,128.52 396.94,128.78 402.27,128.78
ZQSFP+4_3.3V on TOP: 375.6,81.15 379.03,81.15 379.16,81.28 379.16,86.74 379.03,86.87 375.48,86.87 375.35,86.74 375.35,81.4
ZQSFP+4_3.3V on TOP: 305.24,87.12 309.05,87.12 309.18,87.25 309.18,90.93 308.93,91.18 306.64,91.18 305.12,89.66 305.12,87.25
ZQSFP+4_3.3V on TOP: 286.83,86.99 288.73,86.99 289.75,85.98 293.18,85.98 293.31,86.1 293.31,89.66 293.18,89.79 291.27,89.79 290.89,89.41 286.96,89.41 286.7,89.15 286.7,87.12
ZQSFP+4_3.3V on TOP: 302.83,87.37 302.83,88.64 302.7,88.77 300.67,88.77 300.55,88.64 300.55,87.37 300.67,87.25 302.7,87.25
ZQSFP+4_3.3V on TOP: 333.06,86.87 329.37,86.87 329.25,86.99 329.25,90.68 329.63,91.06 332.93,91.06 333.18,90.8 333.18,86.99
ZQSFP+4_3.3V on TOP: 352.62,93.34 352.74,93.22 352.74,90.93 351.47,89.66 351.47,87.12 347.79,87.12 347.66,87.25 347.66,93.09 347.92,93.34
ZQSFP+4_3.3V on TOP: 358.97,85.72 357.7,85.72 357.06,86.36 357.06,88.77 357.19,88.9 360.49,88.9 360.62,88.77 360.62,87.63 360.36,87.37 359.22,87.37 359.09,87.25 359.09,85.85
ZQSFP+4_3.3V on TOP: 385.38,94.1 385.13,94.36 385.13,98.04 385.38,98.3 387.79,98.3 387.92,98.17 387.92,94.23 387.79,94.1
ZQSFP+4_3.3V on TOP: 304.48,80.9 301.05,80.9 300.8,81.15 300.8,82.8 301.18,83.18 304.36,83.18 304.74,82.8 304.74,81.15
ZQSFP+4_3.3V on TOP: 365.82,81.28 362.14,81.28 362.01,81.4 362.01,82.8 362.27,83.06 362.65,83.06 363.54,83.94 364.81,83.94 364.93,84.07 364.93,85.34 365.32,85.72 366.2,85.72 366.46,85.47 366.46,83.06 366.08,82.67 366.08,81.53
ZQSFP+4_3.3V on TOP, BOTTOM: 348.81,82.8 349.19,83.18 352.36,83.18 352.74,82.8 352.74,80.64 352.62,80.52 348.93,80.52 348.81,80.64
ZQSFP+4_3.3V on TOP, BOTTOM: 319.85,86.87 316.17,86.87 316.04,86.99 316.04,90.68 316.42,91.06 319.6,91.06 319.98,90.68 319.98,86.99
ZQSFP+4_3.3V on TOP, BOTTOM: 319.85,81.02 316.17,81.02 316.04,81.15 316.04,82.8 316.42,83.18 319.6,83.18 319.98,82.8 319.98,81.15
ZQSFP+4_3.3V on TOP, BOTTOM: 389.06,85.98 385.38,85.98 385.25,86.1 385.25,89.79 385.51,90.04 388.94,90.04 389.19,89.79 389.19,86.1
ZQSFP+4_3.3V on TOP, BOTTOM: 389.06,80.13 385.38,80.13 385.25,80.26 385.25,81.91 385.64,82.29 388.81,82.29 389.19,81.91 389.19,80.26
ZQSFP+4_3.3V on TOP, BOTTOM: 333.06,81.02 329.37,81.02 329.25,81.15 329.25,82.8 329.63,83.18 332.8,83.18 333.18,82.8 333.18,81.15
ZQSFP+4_3.3V on BOTTOM: 348.81,87.25 348.81,93.34 348.93,93.47 352.62,93.47 352.74,93.34 352.74,87.25 352.62,87.12 348.93,87.12
ZQSFP+4_3.3V on BOTTOM: 365.82,81.28 362.14,81.28 362.01,81.4 362.01,83.82 362.14,83.94 365.95,83.94 366.08,83.82 366.08,81.53
ZQSFP+4_3.3V on BOTTOM: 304.61,81.02 302.32,81.02 302.07,81.28 302.07,82.93 302.32,83.18 304.36,83.18 304.74,82.8 304.74,81.15
ZQSFP+4_3.3V on BOTTOM: 333.06,86.87 329.37,86.87 329.25,86.99 329.25,93.09 329.63,93.47 333.06,93.47 333.18,93.34 333.18,86.99
ZQSFP+4_3.3V on BOTTOM: 375.6,81.15 377.38,81.15 377.63,81.4 377.63,86.61 377.38,86.87 375.48,86.87 375.35,86.74 375.35,81.4
ZQSFP+4_3.3V on BOTTOM: 402.27,128.9 402.53,128.65 402.53,127.25 404.05,125.73 404.05,115.44 403.67,115.06 397.32,115.06 396.68,115.69 396.68,128.65 396.94,128.9
ZQSFP+4_3.3V on POWER1: 285.69,73.23 285.69,82.72 290,87.04 290,88.43 293.14,91.56 350.52,91.56 350.99,91.11 351.46,91.56 362.82,91.56 365.11,89.28 374.42,89.28 378.02,92.88 378.02,104.94 399.05,125.98 408.54,125.98 408.88,125.64 408.88,115.74 410.06,114.55 427.97,114.55 428.73,113.79 428.98,113.79 428.98,75.18 428.86,75.18 428.1,74.42 400.03,74.42 392.93,67.32 291.6,67.32
N24368090 on TOP: 258.38,216.15 256.48,216.15 254.7,214.37 252.54,214.37 252.29,214.63 252.29,217.93 252.41,218.06 255.33,218.06 256.22,217.17 258.38,217.17 258.64,216.91 258.64,216.41
N26328760 on TOP: 391.48,28.06 393.89,28.06 394.27,27.68 394.27,21.21 394.14,21.08 391.35,21.08 391.1,21.33 391.1,27.68
N26328760 on SIG2: 387.79,22.98 395.54,22.98 395.8,22.73 395.8,8.51 395.54,8.25 387.79,8.25 387.41,8.63 387.41,22.6
N28597003 on TOP (solid shape): 70.24,178.18 70.24,174.08 70.14,173.97 69.06,173.97 68.93,174.1 68.93,175.91 68.34,176.5 68.34,178.31 68.47,178.43 69.99,178.43
N28597003 on TOP (solid shape): 70.24,157.72 70.24,153.77 70.12,153.64 69.05,153.64 69.02,153.67 69.02,155.5 68.83,155.69 68.83,157.68 69.06,157.91 70.06,157.91
N28597003 on TOP (solid shape): 347.09,183.2 347.09,181.42 347.76,180.75 347.76,178.96 347.63,178.84 345.98,178.84 345.85,178.96 345.85,183.18 345.98,183.31 346.98,183.31
N28597003 on TOP (solid shape): 347.13,162.93 347.13,161.08 347.76,160.45 347.76,159 347.63,158.87 345.98,158.87 345.85,159 345.85,162.86 345.98,162.99 347.06,162.99
N28597003 on TOP (solid shape): 347.13,142.6 347.13,140.75 347.76,140.13 347.76,138.32 347.63,138.2 346.1,138.2 345.85,138.45 345.85,142.54 345.98,142.67 347.06,142.67
N28597003 on TOP (solid shape): 347.08,173.05 347.08,171.29 347.83,170.53 350.3,170.53 352.11,172.34 361.63,172.34 361.89,172.08 361.89,168.65 361.63,168.4 350.79,168.4 350.74,168.45 348.71,168.45 348.66,168.4 346.01,168.4 345.85,168.56 345.85,173.02 345.98,173.15 346.98,173.15
N28597003 on TOP (solid shape): 59.7,151.6 59.72,151.6 59.74,151.59 63.22,148.1 68.12,148.1 68.39,147.83 70.12,147.83 70.24,147.7 70.24,143.61 70.12,143.48 68.97,143.48 68.85,143.61 68.85,145.51 68.06,146.3 56.55,146.3 55.21,147.64 55.21,150.93 55.89,151.6
N28597003 on TOP (solid shape): 347.09,152.71 347.09,150.95 348.06,149.98 350.2,149.98 351.73,151.51 361.76,151.51 362.01,151.25 362.01,147.83 361.76,147.57 355.79,147.57 354.14,149.22 348.04,149.22 347.53,148.71 346.01,148.71 345.87,148.85 345.85,148.87 345.85,148.89 345.85,152.7 345.98,152.83 346.98,152.83
N28597003 on TOP (solid shape): 347.25,132.38 347.25,130.48 347.93,129.79 350.6,129.79 350.88,130.07 350.88,131.34 351.01,131.47 354.75,131.47 355.28,130.93 355.28,127.63 354.65,127 351.16,127 351.15,127 350.77,127.03 350.38,127 350.38,127 347.55,127 347.13,127.13 346.71,127.01 346.7,127 346.65,127 346.27,127.38 346.27,128.87 345.85,129.28 345.85,132.38 345.98,132.51 347.12,132.51
N28597003 on TOP (solid shape): 63.37,168.22 63.57,168.22 63.83,167.95 67.25,167.95 67.6,168.02 67.9,168.22 69.79,168.22 70.24,167.76 70.24,163.93 70.12,163.8 69.08,163.8 69.02,163.86 69.02,165.66 68.06,166.62 65.47,166.62 64.63,165.79 64.6,165.78 64.59,165.79 64.25,165.83 63.92,165.71 60.87,165.71 60.84,165.72 60.82,165.75 60.13,166.22 59.45,165.75 59.43,165.72 59.4,165.71 58.85,165.71 58.82,165.72 58.8,165.75 58.12,166.22 57.43,165.75 57.41,165.72 57.38,165.71 56.2,165.71 55.16,166.75 55.16,171.32 55.8,171.96 59.63,171.96
N28597003 on TOP (solid shape): outline of 764 points within 46.75,184.12 71.18,203.07
N28597003 on BOTTOM (solid shape): outline of 1633 points within 46.29,133.35 71.69,202.18
N28597003 on TOP: 68.83,137.52 70.05,137.52 70.25,137.31 70.25,133.4 70.17,133.32 69.01,133.32 68.76,133.57 68.76,137.45
N28597003 on TOP: 357.82,189.74 362.78,189.74 363.16,189.35 363.16,186.56 363.03,186.43 357.95,186.43 357.7,186.69 357.7,189.61
N28597003 on BOTTOM: 345.8,130.49 345.8,132.48 345.93,132.61 346.97,132.61 347.23,132.87 347.23,134.33 346.93,134.64 346.05,134.64 345.8,134.9 345.8,142.28 346.29,142.77 347.06,142.77 347.26,142.97 347.26,144.55 346.88,144.92 345.94,144.92 345.8,145.06 345.8,152.68 345.93,152.8 346.93,152.8 347.3,153.17 347.3,154.58 346.92,154.96 346.05,154.96 345.8,155.22 345.8,162.71 346.05,162.96 346.88,162.96 347.26,163.34 347.26,164.77 346.79,165.25 345.93,165.25 345.8,165.38 345.8,173 345.93,173.12 346.83,173.12 347.25,173.54 347.25,174.91 346.87,175.28 345.93,175.28 345.8,175.41 345.8,183.16 345.93,183.28 350.37,183.28 350.63,183.03 350.63,180.49 347.96,177.82 347.96,175.41 350.5,172.87 350.5,169.57 348.21,167.28 348.21,163.47 350.5,161.18 350.5,159.66 348.47,157.63 348.47,152.8 350.5,150.77 350.5,149.5 347.96,146.96 347.96,143.28 350.63,140.61 350.63,139.21 350.24,138.83 348.34,138.83 347.96,138.45 347.96,135.34 350.63,132.67 350.63,129.78 350.84,129.56 354.88,129.56 355.41,129.03 355.41,126.87 355.03,126.49 349.57,126.49 348.68,125.6 348.68,124.15 348,123.47 344.71,123.47 344.22,123.97 344.22,128.91
N28597003 on SIG3: 384.01,218.21 383.98,204.91 383.98,200.25 383.1,200.25 383.1,198.9 383.98,198.9 383.98,124.84 383.11,123.97 345.91,123.97 345.15,124.73 345.15,157.22 340.96,161.41 327.6,161.41 322.64,166.37 277.94,166.37 252.92,191.39 152.44,191.39 144.48,183.42 117.25,183.42 108.04,192.63 90.3,192.63 89.14,191.47 89.14,189.15 89.19,189.1 89.19,128.13 87.16,126.11 59.63,126.11 51.24,134.49 51.24,180.21 43.75,187.7 43.75,221.61 44.51,222.37 72.96,222.37 74.49,220.85 74.49,212.21 78.04,208.66 78.17,208.66 78.68,208.15 110.17,208.15 124.65,222.63 379.59,222.63 ; 1 cut-out
N30065298 on TOP (solid shape): 17.84,118.87 17.84,111.25 17.08,110.49 9.46,110.49 9.08,110.87 9.08,116.96 9.84,117.73 9.84,119.64 9.92,119.72 10.03,119.72 10.1,119.65 10.1,119.6 10.1,118.99 10.2,118.89 10.26,118.89 10.34,118.97 10.34,119.64 10.41,119.71 10.53,119.71 10.6,119.64 10.6,118.95 10.66,118.89 10.77,118.89 10.84,118.96 10.84,119.64 10.92,119.72 11.04,119.72 11.1,119.65 11.1,118.95 11.16,118.89 11.28,118.89 11.34,118.95 11.34,119.65 11.41,119.71 11.54,119.71 11.6,119.65 11.6,118.98 11.69,118.89 11.75,118.89 11.84,118.98 11.84,119.64 11.91,119.71 12.03,119.71 12.1,119.65 12.1,118.93 12.14,118.89 12.29,118.89 12.34,118.94 12.34,119.65 12.45,119.76 16.96,119.76
N30065298 on BOTTOM (solid shape): 17.84,118.87 17.84,111.25 17.08,110.49 9.46,110.49 9.08,110.87 9.08,116.96 9.84,117.73 9.84,119.64 9.96,119.76 16.95,119.76
N30070694 on TOP (solid shape): 45.53,125.85 45.53,118.23 44.77,117.47 37.15,117.47 36.77,117.85 36.77,123.95 37.53,124.71 37.53,126.63 37.6,126.7 37.71,126.7 37.78,126.63 37.78,125.97 37.88,125.87 37.94,125.87 38.03,125.96 38.03,126.63 38.1,126.7 38.21,126.7 38.28,126.63 38.28,125.94 38.35,125.87 38.46,125.87 38.53,125.94 38.53,126.62 38.61,126.7 38.72,126.7 38.78,126.64 38.78,125.93 38.84,125.87 38.97,125.87 39.03,125.94 39.03,126.64 39.09,126.7 39.22,126.7 39.28,126.64 39.28,125.97 39.38,125.87 39.43,125.87 39.53,125.97 39.53,126.63 39.6,126.7 39.72,126.7 39.78,126.63 39.78,125.92 39.83,125.87 39.98,125.87 40.03,125.93 40.03,126.64 40.14,126.74 44.64,126.74
N30070694 on BOTTOM (solid shape): 45.53,125.85 45.53,118.23 44.77,117.47 37.15,117.47 36.77,117.85 36.77,123.95 37.53,124.71 37.53,126.63 37.65,126.74 44.64,126.74
N30072461 on TOP (solid shape): 396.3,119.12 396.3,111.5 395.92,111.12 389.83,111.12 389.06,111.88 387.15,111.88 387.07,111.96 387.07,112.07 387.14,112.14 387.19,112.14 387.8,112.14 387.9,112.24 387.9,112.3 387.82,112.38 387.15,112.38 387.08,112.46 387.08,112.57 387.15,112.64 387.84,112.64 387.9,112.71 387.9,112.81 387.83,112.88 387.15,112.88 387.07,112.96 387.07,113.08 387.14,113.14 387.85,113.14 387.9,113.2 387.9,113.32 387.84,113.39 387.14,113.39 387.08,113.45 387.08,113.58 387.14,113.64 387.81,113.64 387.9,113.73 387.9,113.79 387.81,113.88 387.15,113.88 387.08,113.96 387.08,114.07 387.15,114.14 387.86,114.14 387.9,114.19 387.9,114.33 387.85,114.39 387.14,114.39 387.03,114.49 387.03,119 387.92,119.89 395.54,119.89
N30074232 on TOP (solid shape): 396.56,143.13 396.56,135.51 396.18,135.13 390.08,135.13 389.32,135.89 387.4,135.89 387.33,135.96 387.33,136.07 387.4,136.14 388.06,136.14 388.16,136.24 388.16,136.3 388.07,136.39 387.4,136.39 387.33,136.46 387.33,136.57 387.4,136.64 388.09,136.64 388.16,136.71 388.16,136.81 388.09,136.89 387.41,136.89 387.33,136.96 387.33,137.08 387.39,137.14 388.1,137.14 388.16,137.2 388.16,137.33 388.09,137.39 387.39,137.39 387.33,137.45 387.33,137.58 387.39,137.64 388.06,137.64 388.16,137.74 388.16,137.79 388.06,137.89 387.4,137.89 387.33,137.96 387.33,138.08 387.4,138.14 388.11,138.14 388.16,138.19 388.16,138.34 388.1,138.39 387.39,138.39 387.29,138.49 387.29,143 388.18,143.89 395.8,143.89
N32365253 on TOP: 148.59,210.98 147.45,210.98 147.36,211.06 147.36,211.32 147.24,211.44 146.12,211.44 146.01,211.33 146.01,210.15 146.1,210.06 147.2,210.06 147.55,210.41 148.57,210.41 148.59,210.43
N32365253 on TOP: 133.59,212.16 139.51,212.16 139.89,211.78 139.89,207.39 139.64,207.13 135.06,207.13 132.65,209.55 132.65,211.22
N32365253 on SIG9: 133.54,212.47 149.29,212.47 149.92,211.83 149.92,207.26 148.91,206.25 135.95,206.25 132.65,209.55 132.65,211.58
N32365530 on TOP (solid shape): 369.38,109.6 369.38,105.53 369.25,105.41 366.84,105.41 366.71,105.53 366.71,109.6 366.84,109.73 369.25,109.73
N32365530 on TOP (solid shape): 366.24,117.44 366.24,115.87 366.28,115.87 366.32,115.85 366.33,115.82 366.33,114.81 366.2,114.68 365.06,114.68 364.93,114.81 364.93,115.95 365.06,116.08 365.57,116.08 365.7,116.2 365.7,117.35 365.82,117.47 366.2,117.47
N32365530 on SIG4 (solid shape): outline of 380 points within 363.28,107.95 368.87,116.46
N32696851 on TOP (solid shape): 376.75,197.99 376.75,195.58 376.62,195.45 372.55,195.45 372.43,195.58 372.43,197.99 372.55,198.12 376.62,198.12
N32696851 on TOP (solid shape): 383.1,199.77 383.1,199.26 383.22,199.13 384.37,199.13 384.49,199.01 384.49,198.63 384.37,198.5 381.83,198.5 381.7,198.63 381.7,199.77 381.83,199.9 382.97,199.9
N32696851 on SIG4: 374.59,202.18 382.84,202.18 383.73,201.29 383.73,195.45 382.84,194.56 374.71,194.56 373.95,195.32 373.95,201.55
N32816680 on TOP (solid shape): 371.28,212.85 371.28,210.44 371.16,210.31 367.09,210.31 366.97,210.44 366.97,212.85 367.09,212.98 371.16,212.98
N32816680 on TOP (solid shape): 377.63,214.63 377.63,214.12 377.76,213.99 378.9,213.99 379.03,213.87 379.03,213.48 378.9,213.36 376.36,213.36 376.24,213.48 376.24,214.63 376.36,214.75 377.51,214.75
N32816680 on SIG4 (solid shape): outline of 301 points within 369.63,209.42 378.14,215.01

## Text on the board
Ref Des/Silkscreen Bottom: A5 | A4 | A3 | A6 | A7 | A2 | A1 | A8 | RE.102C02051S1,16978
User.Comments: BL_BCM56873_M0_SCHEMATIC1_455396 | BL_BCM56970_M0_SCHEMATIC1_494704
Ref Des/Silkscreen Top: A | H | JTAG_TEST | GND | B | CPLD_DOWNLOAD | 1.24V | ZQSFP+2_3.3V | C | G | D | E | F | VDD1.8V | VDD1.2V | A1 | VDD3.3_CLK_MCU | z | ANLGOUT | VDD_CORE | C1 | D1 | CPLD3.3V | B1 | VDD5.0V | PWR_DOWNLOAD | ZQSFP+1_3.3V | VDD3.3V | ZQSFP+4_3.3V | ZQSFP+3_3.3V | MAC ADDRESS | 02FEBZ-FD0317 V1.02 | S/N1 | SOFT | S/N2
DIMENSION: BACKDRILL_B:NULL:B-S10@TOP-SIG10@ | BACKDRILL_B:NULL:T-S4@BOTTOM-SIG4@ | BACKDRILL_B:NULL:B-S9@SIG9@TOP-SIG9@ | BACKDRILL_B:NULL:B-S7@TOP-SIG7@ | BACKDRILL_B:NULL:T-S9@BOTTOM-SIG9@ | BACKDRILL_B:NULL:T-S8@BOTTOM-SIG8@ | BACKDRILL_B:NULL:T-S7@BOTTOM-SIG7@ | BACKDRILL_B:NULL:T-S6@BOTTOM-SIG6@ | BACKDRILL_B:NULL:B-S5@TOP-SIG5@ | BACKDRILL_B:BGA:B-S9@TOP-SIG9@ | BACKDRILL_B:BGA:B-S8@TOP-SIG8@ | BACKDRILL_B:BGA:B-S7@TOP-SIG7@ | BACKDRILL_B:BGA:B-S6@TOP-SIG6@ | BACKDRILL_B:BGA:B-S5@TOP-SIG5@ | BACKDRILL_B:BGA:B-S4@TOP-SIG4@ | BACKDRILL_B:BGA:B-S3@TOP-SIG3@ | BACKDRILL_B:BGA:B-S2@TOP-SIG2@ | BACKDRILL_B:NULL:B-S2@TOP-SIG2@ | BACKDRILL_B:NULL:B-S3@TOP-SIG3@ | BACKDRILL_B:NULL:B-S4@TOP-SIG4@
User.5: MAC POWER SHAPE DO NOT CHANGE | GND1,GND12
User.6: 4mm
User.34: FIGURE | SIZE | 8.0 | 9.0 | 14.57 | 16.0 | 20.0 | 35.43 | 41.34 | 43.31 | 47.24 | 61.81 | 72.05 | 86.61 | 137.8 | 216.54 | 98.43 | 122.05 | 127.95 | 57.09x41.34 | 59.06x39.37 | 114.17x98.43 | DRILL CHART: TOP to BOTTOM | ALL UNITS ARE IN MILS | PLATED | NON-PLATED | QTY | 1058 | 9799 | 2504 | 1379 | 128 | 2 | 4 | 144 | 20 | 5 | 34 | 16 | 80
